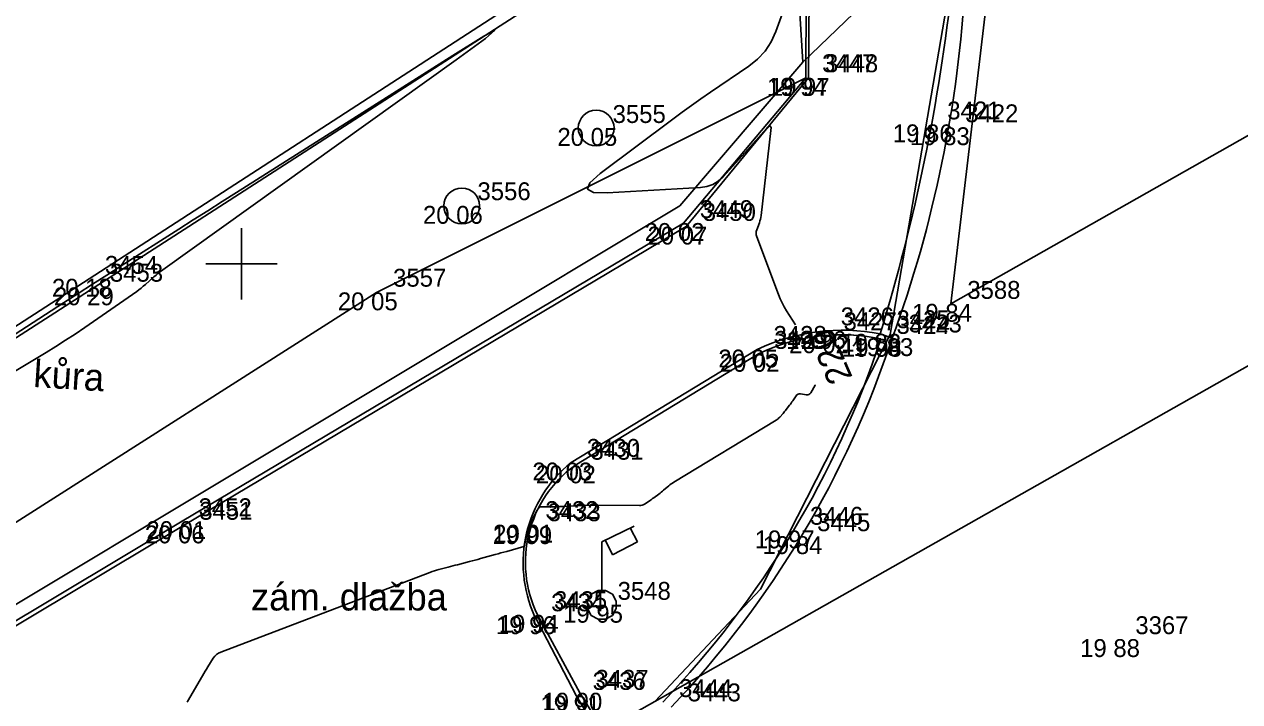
# Model space of a CAD drawing. Extents: x -702257 to -701487, y -1009871 to -1008841.
# Drawn here: x -702103.04 to -702086.04, y -1009681.12 to -1009671.65 of the extents above; entities that cross this region are included whole.
import ezdxf

# ---------------------------------------------------------------- set-up
doc = ezdxf.new("R2010")
doc.units = 0
for name, color, linetype in [('Ex_Contour Labels', 7, 'Continuous'), ('Ex_Major Contours', 7, 'Continuous'), ('Ex_Minor Contours', 7, 'Continuous'), ('Z_body', 7, 'Continuous'), ('Z_body_cisla', 7, 'Continuous'), ('Z_body_vysky_redukovane', 7, 'Continuous'), ('Z_hektometricka_sit', 7, 'Continuous'), ('Z_katastr_hranice', 7, 'Continuous'), ('Z_komunikace', 7, 'Continuous'), ('Z_obruba', 7, 'Continuous'), ('Z_popisy', 7, 'Continuous'), ('Z_rozhranni', 7, 'Continuous'), ('Z_site_vo_znaky', 7, 'Continuous'), ('Z_vdz_prechod', 7, 'Continuous'), ('Z_zelen_jednotliva', 7, 'Continuous')]:
    doc.layers.add(name, color=color, linetype=linetype)

# ---------------------------------------------------------------- blocks, each defined once
blk = doc.blocks.new('POINT_DISPLAY')
blk.add_line((0, 0), (0, 0))
blk = doc.blocks.new('Z10001')
blk.add_circle((0, 0), 0.25)
blk = doc.blocks.new('Z13')
for p, q in [((0, 0.88), (0.45, 1.1)), ((0.4, 1.07), (0.5, 0.88)), ((0, 0.2), (0, 0.88)), ((0.15, 0.7), (0.05, 0.9)), ((0.5, 0.88), (0.15, 0.7)), ((-0.15, 0.15), (-0.05, 0.2)), ((-0.05, 0.2), (0.05, 0.2)), ((0.05, 0.2), (0.15, 0.15)), ((-0.2, 0.05), (-0.15, 0.15)), ((-0.2, -0.05), (-0.2, 0.05)), ((0.15, 0.15), (0.2, 0.05)), ((0.2, 0.05), (0.2, -0.05)), ((-0.15, -0.15), (-0.2, -0.05)), ((-0.05, -0.2), (-0.15, -0.15)), ((0.15, -0.15), (0.05, -0.2)), ((0.2, -0.05), (0.15, -0.15)), ((0.05, -0.2), (-0.05, -0.2))]:
    blk.add_line(p, q)

msp = doc.modelspace()

# ---------------------------------------------------------------- linework, layer by layer
at = {"layer": 'Ex_Major Contours'}
for points in [[(-702092.134, -1009670.67), (-702092.528, -1009671.75), (-702092.593, -1009671.895), (-702092.678, -1009672.024), (-702092.782, -1009672.138), (-702092.906, -1009672.236), (-702093.441, -1009672.6), (-702093.574, -1009672.692), (-702093.706, -1009672.785), (-702093.837, -1009672.88), (-702093.967, -1009672.976), (-702094.984, -1009673.738), (-702095.127, -1009673.867), (-702095.159, -1009673.955), (-702095.078, -1009674.002), (-702094.885, -1009674.008), (-702093.582, -1009673.933), (-702093.491, -1009673.92), (-702093.408, -1009673.89), (-702093.332, -1009673.844), (-702093.265, -1009673.782), (-702092.956, -1009673.443), (-702092.919, -1009673.401), (-702092.881, -1009673.36), (-702092.844, -1009673.318), (-702092.806, -1009673.276), (-702092.657, -1009673.108), (-702092.626, -1009673.078), (-702092.605, -1009673.073), (-702092.595, -1009673.092), (-702092.596, -1009673.136), (-702092.732, -1009674.325), (-702092.736, -1009674.35), (-702092.742, -1009674.376), (-702092.749, -1009674.401), (-702092.757, -1009674.426), (-702092.795, -1009674.524), (-702092.802, -1009674.548), (-702092.804, -1009674.573), (-702092.802, -1009674.597), (-702092.795, -1009674.622), (-702092.491, -1009675.429), (-702092.466, -1009675.488), (-702092.439, -1009675.546), (-702092.409, -1009675.603), (-702092.376, -1009675.657), (-702092.251, -1009675.855)], [(-702091.518, -1009675.99), (-702091.495, -1009675.991), (-702091.489, -1009675.991), (-702091.477, -1009675.993), (-702091.388, -1009676.003), (-702091.377, -1009676.006), (-702091.371, -1009676.012), (-702091.37, -1009676.02), (-702091.373, -1009676.031), (-702091.397, -1009676.082), (-702091.403, -1009676.093), (-702091.409, -1009676.103), (-702091.416, -1009676.113), (-702091.423, -1009676.123), (-702091.447, -1009676.153)], [(-702091.976, -1009676.693), (-702091.979, -1009676.697), (-702092.039, -1009676.805), (-702092.05, -1009676.82), (-702092.064, -1009676.83), (-702092.08, -1009676.835), (-702092.099, -1009676.834), (-702092.181, -1009676.819), (-702092.2, -1009676.818), (-702092.217, -1009676.822), (-702092.232, -1009676.832), (-702092.244, -1009676.846), (-702092.291, -1009676.916), (-702092.302, -1009676.932), (-702092.313, -1009676.947), (-702092.324, -1009676.962), (-702092.335, -1009676.977), (-702092.383, -1009677.04), (-702092.394, -1009677.053), (-702092.404, -1009677.067), (-702092.415, -1009677.08), (-702092.426, -1009677.093), (-702092.472, -1009677.144), (-702092.484, -1009677.156), (-702092.496, -1009677.168), (-702092.51, -1009677.178), (-702092.524, -1009677.188), (-702093.952, -1009678.054), (-702093.971, -1009678.067), (-702093.99, -1009678.079), (-702094.008, -1009678.093), (-702094.025, -1009678.107), (-702094.097, -1009678.168), (-702094.113, -1009678.181), (-702094.13, -1009678.194), (-702094.147, -1009678.207), (-702094.164, -1009678.22), (-702094.234, -1009678.273), (-702094.25, -1009678.284), (-702094.266, -1009678.296), (-702094.282, -1009678.307), (-702094.298, -1009678.318), (-702094.364, -1009678.361), (-702094.381, -1009678.371), (-702094.399, -1009678.377), (-702094.417, -1009678.381), (-702094.436, -1009678.382), (-702095.209, -1009678.377), (-702095.22, -1009678.377), (-702095.231, -1009678.378), (-702095.243, -1009678.378), (-702095.254, -1009678.379), (-702095.31, -1009678.383), (-702095.333, -1009678.385), (-702095.344, -1009678.386), (-702095.395, -1009678.389), (-702095.419, -1009678.39), (-702095.444, -1009678.392), (-702095.499, -1009678.394), (-702095.526, -1009678.395), (-702095.553, -1009678.396), (-702095.615, -1009678.398), (-702095.645, -1009678.399), (-702095.675, -1009678.4), (-702095.767, -1009678.401), (-702095.788, -1009678.401), (-702095.823, -1009678.401), (-702095.829, -1009678.402), (-702095.835, -1009678.404), (-702095.84, -1009678.408), (-702095.844, -1009678.413), (-702095.874, -1009678.462), (-702095.878, -1009678.469), (-702095.885, -1009678.483), (-702095.888, -1009678.488), (-702095.922, -1009678.56), (-702095.928, -1009678.573), (-702095.934, -1009678.585), (-702095.949, -1009678.62), (-702095.953, -1009678.629), (-702095.96, -1009678.646), (-702095.962, -1009678.652), (-702095.987, -1009678.726), (-702095.999, -1009678.76), (-702096.002, -1009678.769), (-702096.004, -1009678.778), (-702096.011, -1009678.805), (-702096.014, -1009678.814), (-702096.039, -1009678.919), (-702096.041, -1009678.928), (-702096.044, -1009678.946), (-702096.045, -1009678.949), (-702096.046, -1009678.951), (-702096.048, -1009678.953), (-702096.051, -1009678.954), (-702096.289, -1009679.022), (-702096.33, -1009679.033), (-702096.371, -1009679.045), (-702096.412, -1009679.056), (-702096.453, -1009679.067), (-702096.657, -1009679.123), (-702096.696, -1009679.134), (-702096.734, -1009679.144), (-702096.773, -1009679.155), (-702096.811, -1009679.165), (-702096.978, -1009679.209), (-702097.01, -1009679.217), (-702097.043, -1009679.226), (-702097.075, -1009679.234), (-702097.108, -1009679.243), (-702097.239, -1009679.276), (-702097.271, -1009679.284), (-702097.303, -1009679.294), (-702097.335, -1009679.305), (-702097.367, -1009679.316), (-702100.288, -1009680.43), (-702100.32, -1009680.445), (-702100.349, -1009680.464), (-702100.373, -1009680.488), (-702100.394, -1009680.516), (-702100.471, -1009680.638), (-702100.491, -1009680.669), (-702100.509, -1009680.7), (-702100.528, -1009680.731), (-702100.546, -1009680.762), (-702100.753, -1009681.12), (-702100.761, -1009681.132)]]:
    msp.add_lwpolyline(points, dxfattribs=at)
at = {"layer": 'Ex_Minor Contours'}
msp.add_lwpolyline([(-702110.263, -1009680.758), (-702102.732, -1009676.24), (-702102.595, -1009676.156), (-702102.459, -1009676.07), (-702102.325, -1009675.982), (-702102.193, -1009675.891), (-702101.466, -1009675.387), (-702101.434, -1009675.364), (-702101.403, -1009675.34), (-702101.373, -1009675.315), (-702101.343, -1009675.289), (-702101.225, -1009675.184), (-702101.195, -1009675.158), (-702101.165, -1009675.133), (-702101.134, -1009675.109), (-702101.102, -1009675.086), (-702097, -1009672.148), (-702096.59, -1009671.849), (-702096.461, -1009671.738), (-702096.612, -1009671.817), (-702097.043, -1009672.085), (-702100.07, -1009674.002), (-702100.271, -1009674.13), (-702100.473, -1009674.258), (-702100.675, -1009674.387), (-702100.876, -1009674.515), (-702101.682, -1009675.029), (-702101.884, -1009675.158), (-702102.085, -1009675.287), (-702102.286, -1009675.417), (-702102.487, -1009675.546), (-702109.536, -1009680.115)], dxfattribs=at)
at = {"layer": 'Z_hektometricka_sit'}
for p, q in [((-702100, -1009674.5), (-702100, -1009675.5)), ((-702100.5, -1009675), (-702099.5, -1009675))]:
    msp.add_line(p, q, dxfattribs=at)
at = {"layer": 'Z_katastr_hranice'}
for p, q in [((-702092.53, -1009666.15), (-702092.15, -1009672.18)), ((-702092.15, -1009672.18), (-702089.9, -1009670.01)), ((-702089.9, -1009670.01), (-702090.93, -1009675.99)), ((-702093.87, -1009674.19), (-702092.15, -1009672.18)), ((-702123.76, -1009692.13), (-702093.87, -1009674.19)), ((-702094.22, -1009681.12), (-702083.93, -1009675.3)), ((-702090.93, -1009675.99), (-702092.74, -1009679.55)), ((-702092.74, -1009679.55), (-702094.22, -1009681.12)), ((-702094.22, -1009681.12), (-702124.35, -1009698.15))]:
    msp.add_line(p, q, dxfattribs=at)
at = {"layer": 'Z_komunikace'}
msp.add_arc((-702106.996, -1009670.149), 17.14, 339.897, 356.9526, dxfattribs=at)
msp.add_ellipse((-702103.889, -1009671.764), major_axis=(6.379, 12.123), ratio=0.998189, start_param=4.435754, end_param=4.87842, dxfattribs=at)
at = {"layer": 'Z_obruba'}
for p, q in [((-702092.11, -1009672.4), (-702092.1, -1009669.98)), ((-702092.05, -1009669.98), (-702092.07, -1009672.4)), ((-702096.11, -1009671.31), (-702102.13, -1009675.21)), ((-702102.06, -1009675.33), (-702095.9, -1009671.36)), ((-702092.11, -1009672.4), (-702093.82, -1009674.43)), ((-702093.78, -1009674.48), (-702092.07, -1009672.4)), ((-702093.82, -1009674.43), (-702100.83, -1009678.6)), ((-702100.81, -1009678.66), (-702093.78, -1009674.48)), ((-702102.13, -1009675.21), (-702111, -1009680.92)), ((-702110.91, -1009681.02), (-702102.06, -1009675.33)), ((-702091.07, -1009675.98), (-702090.9, -1009676.04)), ((-702095.39, -1009677.78), (-702092.79, -1009676.2)), ((-702092.77, -1009676.26), (-702095.34, -1009677.82)), ((-702100.83, -1009678.6), (-702109.15, -1009683.58)), ((-702109.13, -1009683.63), (-702100.81, -1009678.66)), ((-702095.32, -1009681.04), (-702095.9, -1009679.93)), ((-702095.27, -1009681), (-702095.86, -1009679.91)), ((-702094.86, -1009681.8), (-702095.32, -1009681.04)), ((-702095.27, -1009681), (-702094.74, -1009681.85))]:
    msp.add_line(p, q, dxfattribs=at)
for centre, major_axis, ratio, start_param, end_param in [((-702115.569, -1009668.365), (4.581, 25.556), 0.987978, 4.589889, 4.783267), ((-702091.687, -1009678.597), (-2.251, -1.553), 0.963846, 3.895155, 4.545693), ((-702103.71, -1009671.908), (4.11, 12.667), 0.99955, 4.260978, 4.709686), ((-702091.625, -1009678.591), (-2.542, -0.681), 0.986381, 4.237226, 4.904365), ((-702094.255, -1009679.183), (-1.566, -0.901), 0.999055, 4.870155, 6.186836), ((-702094.345, -1009679.177), (-1.663, -0.265), 0.999186, 5.186735, 6.575911)]:
    msp.add_ellipse(centre, major_axis=major_axis, ratio=ratio, start_param=start_param, end_param=end_param, dxfattribs=at)
at = {"layer": 'Z_rozhranni'}
for p, q in [((-702098.11, -1009675.4), (-702092.11, -1009672.4)), ((-702104.14, -1009679.24), (-702098.11, -1009675.4))]:
    msp.add_line(p, q, dxfattribs=at)
at = {"layer": 'Z_vdz_prechod'}
for p, q in [((-702090.08, -1009675.56), (-702089.53, -1009670.91)), ((-702082.63, -1009671.34), (-702090.08, -1009675.56))]:
    msp.add_line(p, q, dxfattribs=at)

# ---------------------------------------------------------------- block references
at = {"layer": 'Z_body'}
for p in [(-702092.11, -1009672.4), (-702092.07, -1009672.4), (-702095.04, -1009673.1), (-702090.35, -1009673.05), (-702090.11, -1009673.09), (-702096.92, -1009674.19), (-702093.82, -1009674.43), (-702093.78, -1009674.48), (-702102.13, -1009675.21), (-702102.06, -1009675.33), (-702098.11, -1009675.4), (-702090.08, -1009675.56), (-702091.84, -1009675.94), (-702091.8, -1009676), (-702091.07, -1009675.98), (-702091.06, -1009676.05), (-702090.9, -1009676.04), (-702092.79, -1009676.2), (-702092.77, -1009676.26), (-702095.39, -1009677.78), (-702095.34, -1009677.82), (-702100.83, -1009678.6), (-702100.81, -1009678.66), (-702095.98, -1009678.65), (-702095.95, -1009678.67), (-702092.28, -1009678.73), (-702092.17, -1009678.81), (-702094.96, -1009679.77), (-702095.9, -1009679.93), (-702095.86, -1009679.91), (-702087.73, -1009680.25), (-702095.32, -1009681.04), (-702095.27, -1009681)]:
    msp.add_blockref('POINT_DISPLAY', p, dxfattribs=at)
at = {"layer": 'Z_site_vo_znaky'}
msp.add_blockref('Z13', (-702094.96, -1009679.77), dxfattribs=at)
at = {"layer": 'Z_zelen_jednotliva'}
for p in [(-702095.04, -1009673.1), (-702096.92, -1009674.19)]:
    msp.add_blockref('Z10001', p, dxfattribs=at)

# ---------------------------------------------------------------- texts
at = {"layer": 'Ex_Contour Labels'}
msp.add_text('220', height=0.35, rotation=113.449, dxfattribs=at).set_placement((-702091.449, -1009676.588))
at = {"layer": 'Z_body_cisla'}
for s, p in [('3447', (-702091.88, -1009672.32)), ('3448', (-702091.84, -1009672.32)), ('3555', (-702094.81, -1009673.03)), ('3421', (-702090.13, -1009672.98)), ('3422', (-702089.88, -1009673.02)), ('3556', (-702096.7, -1009674.11)), ('3449', (-702093.59, -1009674.36)), ('3450', (-702093.55, -1009674.4)), ('3454', (-702101.91, -1009675.14)), ('3453', (-702101.84, -1009675.25)), ('3557', (-702097.88, -1009675.32)), ('3588', (-702089.85, -1009675.49)), ('3426', (-702091.62, -1009675.86)), ('3427', (-702091.58, -1009675.93)), ('3425', (-702090.84, -1009675.9)), ('3423', (-702090.67, -1009675.96)), ('3428', (-702092.56, -1009676.12)), ('3424', (-702090.84, -1009675.98)), ('3429', (-702092.55, -1009676.19)), ('3430', (-702095.17, -1009677.7)), ('3431', (-702095.12, -1009677.74)), ('3452', (-702100.6, -1009678.53)), ('3451', (-702100.59, -1009678.58)), ('3432', (-702095.75, -1009678.57)), ('3433', (-702095.72, -1009678.6)), ('3446', (-702092.05, -1009678.65)), ('3445', (-702091.95, -1009678.74)), ('3548', (-702094.74, -1009679.7)), ('3434', (-702095.67, -1009679.86)), ('3435', (-702095.63, -1009679.83)), ('3367', (-702087.5, -1009680.18)), ('3436', (-702095.09, -1009680.96)), ('3437', (-702095.05, -1009680.93)), ('3444', (-702093.88, -1009681.06)), ('3443', (-702093.76, -1009681.12))]:
    msp.add_text(s, height=0.25, dxfattribs=at).set_placement(p)
at = {"layer": 'Z_body_vysky_redukovane'}
for s, p in [('19 94', (-702092.652, -1009672.65)), ('19 97', (-702092.612, -1009672.65)), ('20 05', (-702095.582, -1009673.35)), ('19 86', (-702090.892, -1009673.3)), ('19 83', (-702090.652, -1009673.34)), ('20 06', (-702097.462, -1009674.44)), ('20 02', (-702094.362, -1009674.68)), ('20 07', (-702094.322, -1009674.73)), ('20 18', (-702102.651, -1009675.46)), ('20 29', (-702102.623, -1009675.58)), ('20 05', (-702098.652, -1009675.65)), ('19 84', (-702090.622, -1009675.81)), ('19 96', (-702092.382, -1009676.19)), ('20 02', (-702092.342, -1009676.25)), ('19 83', (-702091.612, -1009676.23)), ('19 98', (-702091.602, -1009676.3)), ('19 83', (-702091.442, -1009676.29)), ('20 05', (-702093.332, -1009676.45)), ('20 02', (-702093.312, -1009676.51)), ('20 03', (-702095.932, -1009678.03)), ('20 02', (-702095.882, -1009678.07)), ('20 01', (-702101.33, -1009678.85)), ('20 06', (-702101.352, -1009678.91)), ('19 99', (-702096.492, -1009678.92)), ('20 01', (-702096.48, -1009678.9)), ('19 97', (-702092.822, -1009678.98)), ('19 84', (-702092.712, -1009679.06)), ('19 95', (-702095.502, -1009680.02)), ('19 96', (-702096.442, -1009680.18)), ('19 94', (-702096.402, -1009680.16)), ('19 88', (-702088.272, -1009680.5)), ('19 91', (-702095.82, -1009681.29)), ('19 90', (-702095.791, -1009681.25))]:
    msp.add_text(s, height=0.25, dxfattribs=at).set_placement(p)
at = {"layer": 'Z_popisy'}
msp.add_text('kůra', height=0.38, rotation=356.4, dxfattribs=at).set_placement((-702102.918, -1009676.722))
msp.add_text('zám. dlažba', height=0.38, dxfattribs=at).set_placement((-702099.867, -1009679.849))

doc.saveas('drawing.dxf')
